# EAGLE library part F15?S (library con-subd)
SUB-D
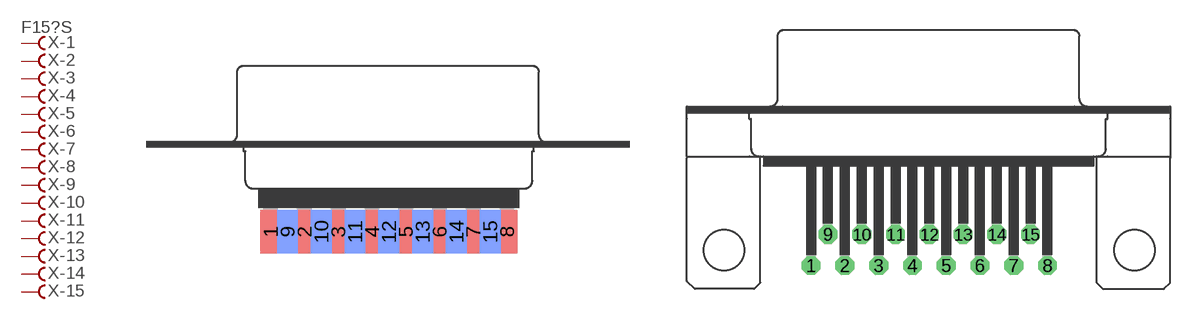
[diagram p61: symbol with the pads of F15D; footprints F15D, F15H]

Designator prefix X; gates -1=FV -2=F -3=F -4=F -5=F -6=F -7=F -8=F -9=F -10=F -11=F -12=F -13=F -14=F -15=F

## F15DS (OC_FARNELL: unknown; OC_NEWARK: unknown)  [F15D]
1  -1:F  pas
2  -2:F  pas
3  -3:F  pas
4  -4:F  pas
5  -5:F  pas
6  -6:F  pas
7  -7:F  pas
8  -8:F  pas
9  -9:F  pas
10  -10:F  pas
11  -11:F  pas
12  -12:F  pas
13  -13:F  pas
14  -14:F  pas
15  -15:F  pas

## F15HS (OC_FARNELL: unknown; OC_NEWARK: unknown)  [F15H]
Pads as for F15D

## F15HPS (OC_FARNELL: unknown; OC_NEWARK: unknown)  [F15HP]
Pads as for F15D

## F15VS (OC_FARNELL: unknown; OC_NEWARK: unknown)  [F15V]
Pads as for F15D

## F15VPS (OC_FARNELL: unknown; OC_NEWARK: unknown)  [F15VP]
Pads as for F15D

## F15HDHS (OC_FARNELL: unknown; OC_NEWARK: unknown)  [HDF15H]
Pads as for F15D

## F15HDVS (OC_FARNELL: unknown; OC_NEWARK: unknown)  [HDF15V]
Pads as for F15D

## F15VBS (OC_FARNELL: unknown; OC_NEWARK: unknown)  [F15VB]
Pads as for F15D

## F15.590S (OC_FARNELL: unknown; OC_NEWARK: unknown)  [177-015-212-FEMALE]
Pads as for F15D

## Footprint F15D (pad centres in mm)
SUB-D
smd 1.7 x 3.5: 1 -9.601,-6.045; 2 -6.858,-6.045; 3 -4.115,-6.045; 4 -1.372,-6.045; 5 1.372,-6.045; 6 4.115,-6.045; 7 6.858,-6.045; 8 9.601,-6.045
smd 1.7 x 3.5 bottom: 9 -8.23,-6.045; 10 -5.486,-6.045; 11 -2.743,-6.045; 12 0,-6.045; 13 2.743,-6.045; 14 5.486,-6.045; 15 8.23,-6.045

## Footprint F15H (pad centres in mm)
SUB-D
drill 1.016 octagon: 1 -9.601,-1.27; 2 -6.858,-1.27; 3 -4.115,-1.27; 4 -1.372,-1.27; 5 1.372,-1.27; 6 4.115,-1.27; 7 6.858,-1.27; 8 9.601,-1.27; 9 -8.23,1.27; 10 -5.486,1.27; 11 -2.743,1.27; 12 0,1.27; 13 2.743,1.27; 14 5.486,1.27; 15 8.23,1.27
hole 3.302 at -16.662,0
hole 3.302 at 16.662,0

## Footprint F15HP (pad centres in mm)
SUB-D
drill 1.016 octagon: 1 -9.601,-1.27; 2 -6.858,-1.27; 3 -4.115,-1.27; 4 -1.372,-1.27; 5 1.372,-1.27; 6 4.115,-1.27; 7 6.858,-1.27; 8 9.601,-1.27; 9 -8.23,1.27; 10 -5.486,1.27; 11 -2.743,1.27; 12 0,1.27; 13 2.743,1.27; 14 5.486,1.27; 15 8.23,1.27
drill 3.302 pad 5.08 round: G1 -16.662,0; G2 16.662,0

## Footprint F15V (pad centres in mm)
SUB-D
drill 1.016 octagon: 1 9.601,1.422; 2 6.858,1.422; 3 4.115,1.422; 4 1.372,1.422; 5 -1.372,1.422; 6 -4.115,1.422; 7 -6.858,1.422; 8 -9.601,1.422; 9 8.23,-1.422; 10 5.486,-1.422; 11 2.743,-1.422; 12 0,-1.422; 13 -2.743,-1.422; 14 -5.486,-1.422; 15 -8.23,-1.422
hole 3.302 at 16.662,0
hole 3.302 at -16.662,0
